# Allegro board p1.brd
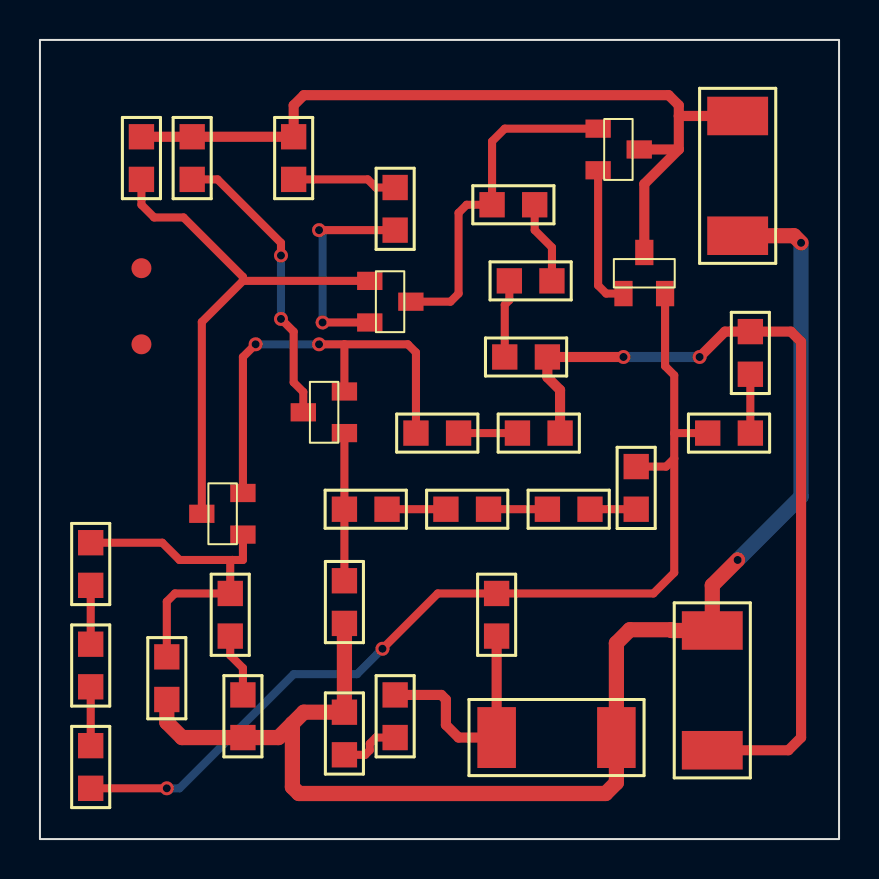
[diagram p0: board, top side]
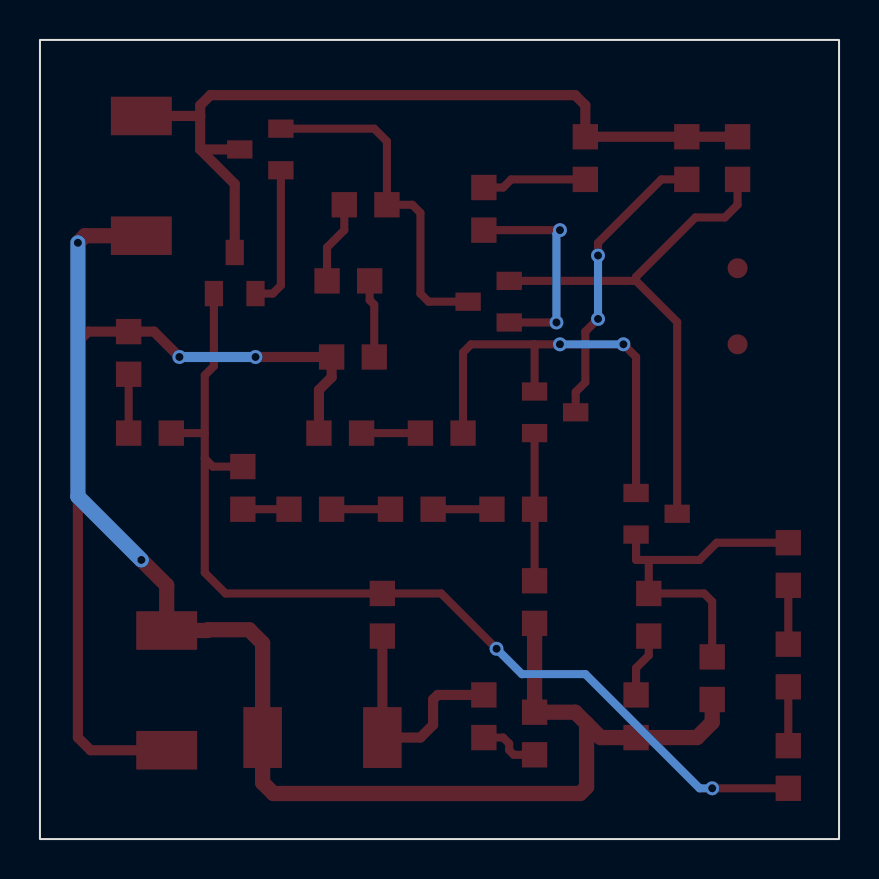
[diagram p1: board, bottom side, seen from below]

Outline 40 x 40 mm; copper layers: TOP, BOTTOM. Coordinates in mm from the lower left corner of the outline.
Outline path: rectangle 0,0 40,40

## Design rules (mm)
nets with their own width: min track width 0.406; nets N26441 N26445 N26529 N26571 N26607 N26701 N26745 N26773 N27689 N27789 N27965 N28453 N264291 N266470 N268210 N268611 N269051 N270770 N277350 N280951 N281291
nets with their own width: min track width 0.508; nets OUT V+ V-
nets with their own width: min track width 0.762; nets GND

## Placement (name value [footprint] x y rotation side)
C1  10u  [SMC0805]  29.84 16.51 90 top
C2  4.7n  [SMC0805]  2.54 2.54 90 top
C3  4.7n  [SMC0805]  6.35 6.99 90 top
C4  10u  [SMC0805]  22.86 10.16 90 top
J2  CON2  [SMR2512]  34.92 36.2 270 top
J3  CON2  [SMR2512]  33.66 4.45 90 top
J5  CON2  [SMR2512]  22.86 5.08 0 top
NOREF  -  [unnamed]  5.08 24.77 0 top
NOREF#2  -  [unnamed]  5.08 28.57 0 top
Q18  BC856B  [TO236AA]  16.51 27.94 180 top
Q19  BC846B  [TO236AA]  27.94 35.56 180 top
Q21  BC846B  [TO236AA]  10.16 15.24 0 top
Q22  BC846B  [TO236AA]  15.24 20.32 0 top
Q23  BC846B  [TO236AA]  29.21 27.3 270 top
R1  51  [SMR0805]  12.7 33.02 90 top
R3  1k  [SMR0805]  7.62 33.02 90 top
R6  10k  [SMR0805]  15.24 10.79 90 top
R7  3.3k  [SMR0805]  24.77 31.75 180 top
R8  680  [SMR0805]  35.56 20.32 180 top
R9  15k  [SMR0805]  15.24 16.51 0 top
R11  2.2k  [SMR0805]  2.54 12.7 90 top
R12  2.2k  [SMR0805]  10.16 5.08 90 top
R13  330  [SMR0805]  15.24 6.35 270 top
R14  2.2k  [SMR0805]  26.04 20.32 180 top
R15  510  [SMR0805]  17.78 30.48 90 top
R16  2.7k  [SMR0805]  20.32 16.51 0 top
R17  3.3k  [SMR0805]  25.4 16.51 0 top
R18  22  [SMR0805]  35.56 25.4 270 top
R19  22  [SMR0805]  17.78 5.08 90 top
R20  330  [SMR0805]  23.5 27.94 0 top
R21  51  [SMR0805]  25.4 24.13 180 top
R22  100  [SMR0805]  20.95 20.32 180 top
R23  68  [SMR0805]  9.53 10.16 90 top
R24  68  [SMR0805]  2.54 7.62 90 top
R*  1k  [SMR0805]  5.08 33.02 90 top

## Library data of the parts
C1-C4 = C
J2 J3 J5 = CON2
Q18 = BC856B
Q19 Q21-Q23 = BC846B
R1 R3 R6-R9 R11-R24 R* = R

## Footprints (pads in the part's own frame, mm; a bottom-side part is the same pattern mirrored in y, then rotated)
SMC0805
  rect 1.27x1.27 smd: 1(0,0) 2(2.134,0)
SMR0805
  rect 1.27x1.27 smd: 1(0,0) 2(2.134,0)
SMR2512
  rect 1.93x3.048 smd: 1(0,0) 2(5.994,0)
TO236AA
  rect 1.27x0.914 smd: 1(0,0) 2(0,2.083) 3(-2.057,1.041)
unnamed
  round 1 smd: (0,0)

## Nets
GND: C3.1 J2.2 J3.2 J5.2 R6.1 R12.1 R13.1
OUT: C4.1 J5.1 R19.2
V+: J2.1 Q19.3 Q23.3 R1.2 R3.2 R*.2
V-: J3.1 R14.1 R18.1 R21.1
N26441: Q18.1 Q21.3 R*.1
N26445: Q22.3 R3.1
N26529: Q18.3 Q19.1 R7.2
N26571: Q19.2(E) Q23.1
N26607: C1.2 C2.1 C4.2 Q23.2(E) R8.2
N26701: Q22.1 R6.2 R9.1
N26745: C3.2 Q21.1 R11.2 R23.2
N26773: Q21.2(E) Q22.2(E) R22.2
N27689: Q18.2(E) R15.1
N27789: C1.1 R17.2
N27965: R13.2 R19.1
N28453: C2.2 R24.1
N264291: R1.1 R15.2
N266470: R9.2 R16.1
N268210: R12.2 R23.1
N268611: R8.1 R18.2
N269051: R11.1 R24.2
N270770: R14.2 R22.1
N277350: R16.2 R17.1
N280951: R7.1 R20.2
N281291: R20.1 R21.2

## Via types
v1: diameter 0.7, hole 0.4, TOP to BOTTOM, 12 vias

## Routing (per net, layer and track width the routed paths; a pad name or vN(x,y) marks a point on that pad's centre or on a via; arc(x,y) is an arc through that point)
GND: length 71.7
  TOP w0.762: J2.2 37.74,30.2 v1(38.1,29.84) ; 12.64,5.78 11.94,5.08 R12.1 7.11,5.08 6.35,5.84 C3.1 ; 12.64,5.78 12.64,2.6 12.96,2.28 28.32,2.28 28.85,2.82 J5.2 28.85,9.8 29.53,10.48 31.58,10.48 31.62,10.44 J3.2 33.66,12.7 v1(34.92,13.97) ; 12.64,5.78 13.21,6.35 R13.1 R6.1
  BOTTOM w0.762: v1(34.92,13.97) 38.1,17.14 v1(38.1,29.84)
OUT: length 11.8
  TOP w0.508: C4.1 J5.1 20.95,5.08 20.32,5.71 20.32,6.99 20.09,7.21 R19.2
V+: length 41.9
  TOP w0.508: Q23.3 30.25,32.79 31.98,34.52 ; R*.2 R3.2 R1.2 12.7,36.73 13.21,37.24 31.47,37.24 31.98,36.73 31.98,36.2 ; Q19.3 31.98,34.52 ; 31.98,34.52 31.98,36.2 ; 31.98,36.2 J2.1
V-: length 42
  TOP w0.508: v1(33.02,24.13) 34.29,25.4 R18.1 37.59,25.4 38.1,24.89 38.1,5.08 37.47,4.45 J3.1 ; R14.1 26.04,22.48 25.4,23.11 R21.1 v1(29.21,24.13)
  BOTTOM w0.508: v1(29.21,24.13) v1(33.02,24.13)
N26441: length 26.9
  TOP w0.406: 10.16,27.94 8.1,25.88 Q21.3 ; 10.16,27.94 Q18.1 ; 10.16,27.94 10.16,28.14 7.19,31.11 5.71,31.11 5.08,31.75 R*.1
N26445: length 14.7
  TOP w0.406: v1(12.06,26.04) 12.7,25.4 12.7,22.86 13.18,22.38 Q22.3 ; R3.1 8.89,33.02 12.06,29.84 v1(12.06,29.21)
  BOTTOM w0.406: v1(12.06,26.04) v1(12.06,29.21)
N26529: length 17.2
  TOP w0.406: Q19.1 23.27,35.56 22.63,34.92 R7.2 21.36,31.75 20.95,31.34 20.95,27.3 20.55,26.9 Q18.3
N26571: length 7.2
  TOP w0.406: Q23.1 28.35,27.3 27.94,27.71 Q19.2
N26607: length 51.6
  TOP w0.406: Q23.2 31.29,23.67 31.75,23.22 31.75,20.32 ; 31.75,19.05 31.34,18.64 C1.2 ; 31.75,19.05 31.75,13.34 30.71,12.29 C4.2 19.91,12.29 v1(17.14,9.53) ; 31.75,19.05 31.75,20.32 ; v1(6.35,2.54) C2.1 ; 31.75,20.32 R8.2
  BOTTOM w0.406: v1(17.14,9.53) 15.88,8.26 12.7,8.26 6.99,2.54 v1(6.35,2.54)
N26701: length 7.4
  TOP w0.406: R6.2 R9.1 Q22.1
N26745: length 17.1
  TOP w0.406: 9.63,13.97 10.16,13.97 Q21.1 ; 9.63,13.97 6.99,13.97 6.12,14.83 R11.2 ; 9.63,13.97 9.53,13.86 R23.2 6.76,12.29 6.35,11.89 C3.2
N26773: length 22.3
  TOP w0.406: Q21.2 10.16,24.13 v1(10.79,24.77) ; v1(13.97,24.77) 15.24,24.77 ; 15.24,24.77 18.41,24.77 18.82,24.36 R22.2 ; 15.24,24.77 Q22.2
  BOTTOM w0.406: v1(13.97,24.77) v1(10.79,24.77)
N27689: length 10.9
  TOP w0.406: v1(13.97,30.48) R15.1 ; v1(14.15,25.86) Q18.2
  BOTTOM w0.406: v1(14.15,25.86) 14.15,30.3 v1(13.97,30.48)
N27789: length 2.3
  TOP w0.406: C1.1 R17.2
N27965: length 3.1
  TOP w0.406: R13.2 16.28,4.22 16.51,4.45 16.51,4.78 16.81,5.08 R19.1
N28453: length 2.9
  TOP w0.406: C2.2 R24.1
N264291: length 5.2
  TOP w0.406: R15.2 16.81,32.61 16.41,33.02 R1.1
N266470: length 2.9
  TOP w0.406: R16.1 R9.2
N268210: length 3.2
  TOP w0.406: R12.2 10.16,8.56 9.53,9.19 R23.1
N268611: length 2.9
  TOP w0.406: R8.1 R18.2
N269051: length 2.9
  TOP w0.406: R24.2 R11.1
N270770: length 2.9
  TOP w0.406: R22.1 R14.2
N277350: length 2.9
  TOP w0.406: R16.2 R17.1
N280951: length 4.2
  TOP w0.406: R20.2 25.63,29.62 24.77,30.48 R7.1
N281291: length 3.9
  TOP w0.406: R20.1 23.5,26.97 23.27,26.75 R21.2

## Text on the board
Ref Des/Silkscreen Top: Dumitru Alexandru 435C | PDCE 2021-2022 | R2
XSECTION_CHART: *  SURFACE - AIR 0 MIL | L1 TOP CONDUCTOR - COPPER 0.72 MIL | *  DIELECTRIC - FR-4 57.63 MIL | L2 BOTTOM CONDUCTOR - COPPER 0.72 MIL | DESIGN CROSS SECTION CHART | ___________________________ | TOTAL THICKNESS 59.07 MIL | 1-2
NCLEGEND-1-2: FIGURE | FINISHED_SIZE | 15.75 | DRILL CHART: TOP to BOTTOM | ALL UNITS ARE IN MILS | PLATED | QTY | 12
